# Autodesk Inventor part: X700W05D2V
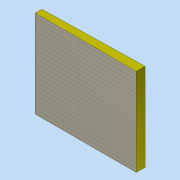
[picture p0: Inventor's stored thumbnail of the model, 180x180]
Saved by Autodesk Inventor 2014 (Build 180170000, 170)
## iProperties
Created: 2012-02
Part Number: X700W05D2V
Document SubType Name: Modeling
Designer: david.appleford
Density: 1 g/cm^3
Description: 1.5w EPS Wedge 1046mm - Second Slope
Mass: 34621.6 g
Surface Area: 13153 cm^2
Volume: 34621.6 cm^3
Cost Center: £15.00
Material: Generic
Appearance: Stucco_01
Justset: False
Title: 1.5w EPS Wedge 1046mm - Second Slope
Author: david.appleford
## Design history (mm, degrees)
sketch "Sketch1"
  geometry: L1 (650.741, -4.894)-(650.741, 25.106); L2 (0, 0)-(807.5, 0); L3 (807.5, 0)-(807.5, 70); L4 (807.5, 70)-(0, 52.5); L5 (0, 52.5)-(0, 0); 1 further point
  constraints: 10 end point, 2 perpendicular, 1 coincident, 1 parallel
  dimensions: "d13" = 807.5 distance between parallel lines of L3 L5; "d14" = 52.5 distance from line of L4.end L2; "d15" = 70 distance of L2.end L3.end
extrude "Extrusion2" new body sketch "Sketch1" distance "d16" = 700; taper "d17" = 0 deg
body "Solid2"
